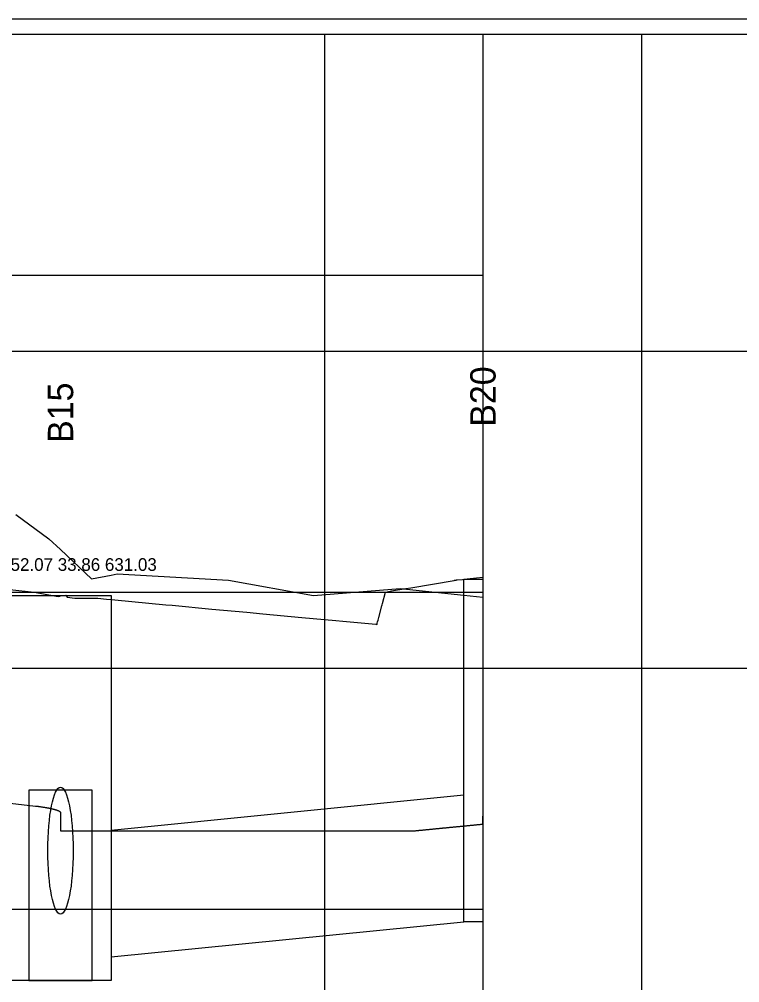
# Model space of a CAD drawing. Extents: x 2253035 to 2279930, y 13774972 to 13793443.
# Drawn here: x 2277850.3 to 2277907.1, y 13792716.5 to 13792792.4 of the extents above; entities that cross this region are included whole.
import ezdxf

# ---------------------------------------------------------------- set-up
doc = ezdxf.new("R2010")
doc.units = 0
for name, color, linetype in [('Default', 7, 'Continuous'), ('E_Utility_ATT_HH', 7, 'Continuous'), ('E_Utility_ATT_PR_PVC', 7, 'Continuous'), ('E_Utility_Telephone_Manhole Telephone_MHT_point', 7, 'Continuous'), ('E_Utility_Telephone_Telephone Pedestal_TPED_Description', 7, 'Continuous'), ('E_Utility_Water_Water Meter_WM_Description', 7, 'Continuous'), ('E_Utillity_Water_Water Line_12in', 7, 'Continuous'), ('E_Utillity_Water_Water Line_1in', 7, 'Continuous'), ('E_Utillity_Water_Water Line_4in', 7, 'Continuous'), ('E_Utillity_Water_Water Line_8in', 7, 'Continuous')]:
    doc.layers.add(name, color=color, linetype=linetype)

msp = doc.modelspace()

# ---------------------------------------------------------------- linework, layer by layer
at = {"layer": 'Default'}
for p, q in [((2277799.404, 13792772.266), (2277886.867, 13792772.266)), ((2277799.404, 13792747.266), (2277886.867, 13792747.266)), ((2277799.404, 13792722.266), (2277886.867, 13792722.266))]:
    msp.add_line(p, q, dxfattribs=at)
msp.add_lwpolyline([(2277799.404, 13792697.266), (2277799.404, 13792791.266), (2277886.867, 13792791.266), (2277886.867, 13792697.266)], close=True, dxfattribs=at)
at = {"layer": 'E_Utility_ATT_PR_PVC'}
msp.add_line((2277853.564, 13792729.873), (2277853.564, 13792728.442), dxfattribs=at)
for points in [[(2277811.207, 13792735.15), (2277851.594, 13792730.392), (2277851.646, 13792730.386), (2277851.695, 13792730.379), (2277851.743, 13792730.373), (2277851.79, 13792730.367), (2277851.835, 13792730.361), (2277851.88, 13792730.355), (2277851.923, 13792730.349), (2277851.966, 13792730.343), (2277852.008, 13792730.337), (2277852.049, 13792730.331), (2277852.089, 13792730.325), (2277852.128, 13792730.319), (2277852.166, 13792730.313), (2277852.204, 13792730.307), (2277852.241, 13792730.301), (2277852.278, 13792730.295), (2277852.313, 13792730.289), (2277852.349, 13792730.283), (2277852.383, 13792730.277), (2277852.417, 13792730.271), (2277852.45, 13792730.265), (2277852.483, 13792730.26), (2277852.515, 13792730.254), (2277852.546, 13792730.248), (2277852.577, 13792730.242), (2277852.607, 13792730.237), (2277852.637, 13792730.231), (2277852.666, 13792730.225), (2277852.695, 13792730.219), (2277852.723, 13792730.214), (2277852.75, 13792730.208), (2277852.777, 13792730.202), (2277852.804, 13792730.197), (2277852.83, 13792730.191), (2277852.855, 13792730.185), (2277852.88, 13792730.18), (2277852.904, 13792730.174), (2277852.928, 13792730.169), (2277852.952, 13792730.163), (2277852.975, 13792730.157), (2277852.997, 13792730.152), (2277853.019, 13792730.146), (2277853.041, 13792730.141), (2277853.062, 13792730.135), (2277853.082, 13792730.13), (2277853.102, 13792730.124), (2277853.122, 13792730.119), (2277853.141, 13792730.113), (2277853.16, 13792730.108), (2277853.178, 13792730.102), (2277853.196, 13792730.097), (2277853.213, 13792730.091), (2277853.23, 13792730.086), (2277853.247, 13792730.081), (2277853.263, 13792730.075), (2277853.278, 13792730.07), (2277853.294, 13792730.064), (2277853.308, 13792730.059), (2277853.323, 13792730.054), (2277853.336, 13792730.048), (2277853.35, 13792730.043), (2277853.363, 13792730.038), (2277853.375, 13792730.032), (2277853.388, 13792730.027), (2277853.399, 13792730.022), (2277853.411, 13792730.016), (2277853.422, 13792730.011), (2277853.432, 13792730.006), (2277853.442, 13792730.001), (2277853.452, 13792729.995), (2277853.461, 13792729.99), (2277853.47, 13792729.985), (2277853.478, 13792729.98), (2277853.486, 13792729.975), (2277853.494, 13792729.969), (2277853.501, 13792729.964), (2277853.508, 13792729.959), (2277853.514, 13792729.954), (2277853.52, 13792729.949), (2277853.526, 13792729.944), (2277853.531, 13792729.938), (2277853.536, 13792729.933), (2277853.541, 13792729.928), (2277853.545, 13792729.923), (2277853.548, 13792729.918), (2277853.551, 13792729.913), (2277853.554, 13792729.908), (2277853.557, 13792729.903), (2277853.559, 13792729.898), (2277853.561, 13792729.893), (2277853.562, 13792729.888), (2277853.563, 13792729.883), (2277853.564, 13792729.878), (2277853.564, 13792729.873)], [(2277853.564, 13792728.442), (2277853.614, 13792728.442), (2277853.664, 13792728.442), (2277853.714, 13792728.442), (2277853.764, 13792728.442), (2277853.815, 13792728.442), (2277853.865, 13792728.442), (2277853.915, 13792728.442), (2277853.965, 13792728.442), (2277854.015, 13792728.442), (2277854.065, 13792728.442), (2277854.115, 13792728.442), (2277854.166, 13792728.442), (2277854.216, 13792728.442), (2277854.266, 13792728.442), (2277854.316, 13792728.442), (2277854.366, 13792728.442), (2277854.416, 13792728.442), (2277854.466, 13792728.442), (2277854.516, 13792728.442), (2277854.567, 13792728.442), (2277854.617, 13792728.442), (2277854.667, 13792728.442), (2277854.717, 13792728.442), (2277854.767, 13792728.442), (2277854.817, 13792728.442), (2277854.867, 13792728.442), (2277854.917, 13792728.442), (2277854.967, 13792728.442), (2277855.018, 13792728.442), (2277855.068, 13792728.442), (2277855.118, 13792728.443), (2277855.168, 13792728.443), (2277855.218, 13792728.443), (2277855.268, 13792728.443), (2277855.318, 13792728.443), (2277855.368, 13792728.443), (2277855.418, 13792728.443), (2277855.468, 13792728.443), (2277855.518, 13792728.443), (2277855.568, 13792728.443), (2277855.618, 13792728.443), (2277855.668, 13792728.443), (2277855.719, 13792728.443), (2277855.769, 13792728.443), (2277855.819, 13792728.443), (2277855.869, 13792728.443), (2277855.919, 13792728.443), (2277855.969, 13792728.443), (2277856.019, 13792728.443), (2277856.069, 13792728.443), (2277856.119, 13792728.443), (2277856.169, 13792728.443), (2277856.219, 13792728.443), (2277856.269, 13792728.443), (2277856.319, 13792728.443), (2277856.369, 13792728.443), (2277856.419, 13792728.443), (2277856.469, 13792728.443), (2277856.519, 13792728.443), (2277856.569, 13792728.443), (2277856.619, 13792728.443), (2277856.669, 13792728.443), (2277856.719, 13792728.443), (2277856.769, 13792728.443), (2277856.819, 13792728.443), (2277856.869, 13792728.443), (2277856.919, 13792728.443), (2277856.969, 13792728.443), (2277857.019, 13792728.443), (2277857.069, 13792728.443), (2277857.12, 13792728.443), (2277857.17, 13792728.443), (2277857.22, 13792728.443), (2277857.27, 13792728.443), (2277857.32, 13792728.443), (2277857.37, 13792728.443), (2277857.42, 13792728.443), (2277857.47, 13792728.443), (2277857.52, 13792728.443), (2277857.57, 13792728.443), (2277857.62, 13792728.443), (2277857.67, 13792728.443), (2277857.72, 13792728.443), (2277857.769, 13792728.443), (2277857.819, 13792728.443), (2277857.869, 13792728.443), (2277857.919, 13792728.443), (2277857.969, 13792728.443), (2277858.019, 13792728.443), (2277858.069, 13792728.443), (2277858.119, 13792728.443), (2277858.169, 13792728.443), (2277858.219, 13792728.443), (2277858.269, 13792728.443), (2277858.319, 13792728.443), (2277858.369, 13792728.443), (2277858.419, 13792728.443), (2277858.469, 13792728.443), (2277858.519, 13792728.443), (2277858.569, 13792728.443), (2277858.619, 13792728.443), (2277858.669, 13792728.443), (2277858.719, 13792728.443), (2277858.769, 13792728.443), (2277858.819, 13792728.443), (2277858.869, 13792728.443), (2277858.919, 13792728.443), (2277858.969, 13792728.443), (2277859.019, 13792728.443), (2277859.069, 13792728.443), (2277859.119, 13792728.443), (2277859.169, 13792728.443), (2277859.219, 13792728.443), (2277859.269, 13792728.443), (2277859.318, 13792728.443), (2277859.368, 13792728.443), (2277859.418, 13792728.443), (2277859.468, 13792728.443), (2277859.518, 13792728.443), (2277859.568, 13792728.443), (2277859.618, 13792728.443), (2277859.668, 13792728.443), (2277859.718, 13792728.443), (2277859.768, 13792728.443), (2277859.818, 13792728.443), (2277859.868, 13792728.443), (2277859.918, 13792728.443), (2277859.968, 13792728.442), (2277860.018, 13792728.442), (2277860.067, 13792728.442), (2277860.117, 13792728.442), (2277860.167, 13792728.442), (2277860.217, 13792728.442), (2277860.267, 13792728.442), (2277860.317, 13792728.442), (2277860.367, 13792728.442), (2277860.417, 13792728.442), (2277860.467, 13792728.442), (2277860.517, 13792728.442), (2277860.567, 13792728.442), (2277860.617, 13792728.442), (2277860.666, 13792728.442), (2277860.716, 13792728.442), (2277860.766, 13792728.442), (2277860.816, 13792728.442), (2277860.866, 13792728.442), (2277860.916, 13792728.442), (2277860.966, 13792728.442), (2277861.016, 13792728.442), (2277861.066, 13792728.442), (2277861.116, 13792728.442), (2277861.165, 13792728.442), (2277861.215, 13792728.442), (2277861.265, 13792728.442), (2277861.315, 13792728.442), (2277861.365, 13792728.442), (2277861.415, 13792728.442), (2277861.465, 13792728.442), (2277861.515, 13792728.442), (2277861.565, 13792728.442), (2277861.614, 13792728.442), (2277861.664, 13792728.442), (2277861.714, 13792728.442), (2277861.764, 13792728.442), (2277861.814, 13792728.442), (2277861.864, 13792728.442), (2277861.914, 13792728.442), (2277861.964, 13792728.442), (2277862.014, 13792728.442), (2277862.063, 13792728.442), (2277862.113, 13792728.442), (2277862.163, 13792728.442), (2277862.213, 13792728.442), (2277862.263, 13792728.442), (2277862.313, 13792728.442), (2277862.363, 13792728.442), (2277862.412, 13792728.442), (2277862.462, 13792728.442), (2277862.512, 13792728.442), (2277862.562, 13792728.442), (2277862.612, 13792728.442), (2277862.662, 13792728.442), (2277862.712, 13792728.442), (2277862.761, 13792728.442), (2277862.811, 13792728.442), (2277862.861, 13792728.442), (2277862.911, 13792728.442), (2277862.961, 13792728.442), (2277863.011, 13792728.442), (2277863.061, 13792728.442), (2277863.11, 13792728.442), (2277863.16, 13792728.442), (2277863.21, 13792728.442), (2277863.26, 13792728.442), (2277863.31, 13792728.442), (2277863.36, 13792728.442), (2277863.41, 13792728.442), (2277863.459, 13792728.442), (2277863.509, 13792728.442), (2277863.559, 13792728.442), (2277863.609, 13792728.442), (2277863.659, 13792728.442), (2277863.709, 13792728.442), (2277863.758, 13792728.442), (2277863.808, 13792728.442), (2277863.858, 13792728.442), (2277863.908, 13792728.442), (2277863.958, 13792728.442), (2277864.007, 13792728.442), (2277864.057, 13792728.442), (2277864.107, 13792728.441), (2277864.157, 13792728.441), (2277864.207, 13792728.441), (2277864.257, 13792728.441), (2277864.306, 13792728.441), (2277864.356, 13792728.441), (2277864.406, 13792728.441), (2277864.456, 13792728.441), (2277864.506, 13792728.441), (2277864.555, 13792728.441), (2277864.605, 13792728.441), (2277864.655, 13792728.441), (2277864.705, 13792728.441), (2277864.755, 13792728.441), (2277864.805, 13792728.441), (2277864.854, 13792728.441), (2277864.904, 13792728.441), (2277864.954, 13792728.441), (2277865.004, 13792728.441), (2277865.054, 13792728.441), (2277865.103, 13792728.441), (2277865.153, 13792728.441), (2277865.203, 13792728.441), (2277865.253, 13792728.441), (2277865.303, 13792728.441), (2277865.352, 13792728.441), (2277865.402, 13792728.441), (2277865.452, 13792728.441), (2277865.502, 13792728.441), (2277865.551, 13792728.441), (2277865.601, 13792728.441), (2277865.651, 13792728.441), (2277865.701, 13792728.441), (2277865.751, 13792728.441), (2277865.8, 13792728.441), (2277865.85, 13792728.441), (2277865.9, 13792728.441), (2277865.95, 13792728.441), (2277865.999, 13792728.441), (2277866.049, 13792728.441), (2277866.099, 13792728.441), (2277866.149, 13792728.441), (2277866.199, 13792728.441), (2277866.248, 13792728.441), (2277866.298, 13792728.441), (2277866.348, 13792728.441), (2277866.398, 13792728.441), (2277866.447, 13792728.441), (2277866.497, 13792728.441), (2277866.547, 13792728.44), (2277866.597, 13792728.44), (2277866.646, 13792728.44), (2277866.696, 13792728.44), (2277866.746, 13792728.44), (2277866.796, 13792728.44), (2277866.845, 13792728.44), (2277866.895, 13792728.44), (2277866.945, 13792728.44), (2277866.995, 13792728.44), (2277867.044, 13792728.44), (2277867.094, 13792728.44), (2277867.144, 13792728.44), (2277867.194, 13792728.44), (2277867.243, 13792728.44), (2277867.293, 13792728.44), (2277867.343, 13792728.44), (2277867.393, 13792728.44), (2277867.442, 13792728.44), (2277867.492, 13792728.44), (2277867.542, 13792728.44), (2277867.592, 13792728.44), (2277867.641, 13792728.44), (2277867.691, 13792728.44), (2277867.741, 13792728.44), (2277867.791, 13792728.44), (2277867.84, 13792728.44), (2277867.89, 13792728.44), (2277867.94, 13792728.44), (2277867.989, 13792728.44), (2277868.039, 13792728.44), (2277868.089, 13792728.44), (2277868.139, 13792728.44), (2277868.188, 13792728.44), (2277868.238, 13792728.44), (2277868.288, 13792728.44), (2277868.337, 13792728.44), (2277868.387, 13792728.44), (2277868.437, 13792728.439), (2277868.487, 13792728.439), (2277868.536, 13792728.439), (2277868.586, 13792728.439), (2277868.636, 13792728.439), (2277868.685, 13792728.439), (2277868.735, 13792728.439), (2277868.785, 13792728.439), (2277868.835, 13792728.439), (2277868.884, 13792728.439), (2277868.934, 13792728.439), (2277868.984, 13792728.439), (2277869.033, 13792728.439), (2277869.083, 13792728.439), (2277869.133, 13792728.439), (2277869.182, 13792728.439), (2277869.232, 13792728.439), (2277869.282, 13792728.439), (2277869.332, 13792728.439), (2277869.381, 13792728.439), (2277869.431, 13792728.439), (2277869.481, 13792728.439), (2277869.53, 13792728.439), (2277869.58, 13792728.439), (2277869.63, 13792728.439), (2277869.679, 13792728.439), (2277869.729, 13792728.439), (2277869.779, 13792728.439), (2277869.828, 13792728.439), (2277869.878, 13792728.439), (2277869.928, 13792728.439), (2277869.977, 13792728.439), (2277870.027, 13792728.438), (2277870.077, 13792728.438), (2277870.126, 13792728.438), (2277870.176, 13792728.438), (2277870.226, 13792728.438), (2277870.275, 13792728.438), (2277870.325, 13792728.438), (2277870.375, 13792728.438), (2277870.424, 13792728.438), (2277870.474, 13792728.438), (2277870.524, 13792728.438), (2277870.573, 13792728.438), (2277870.623, 13792728.438), (2277870.673, 13792728.438), (2277870.722, 13792728.438), (2277870.772, 13792728.438), (2277870.822, 13792728.438), (2277870.871, 13792728.438), (2277870.921, 13792728.438), (2277870.97, 13792728.438), (2277871.02, 13792728.438), (2277871.07, 13792728.438), (2277871.119, 13792728.438), (2277871.169, 13792728.438), (2277871.219, 13792728.438), (2277871.268, 13792728.438), (2277871.318, 13792728.438), (2277871.368, 13792728.438), (2277871.417, 13792728.437), (2277871.467, 13792728.437), (2277871.516, 13792728.437), (2277871.566, 13792728.437), (2277871.616, 13792728.437), (2277871.665, 13792728.437), (2277871.715, 13792728.437), (2277871.765, 13792728.437), (2277871.814, 13792728.437), (2277871.864, 13792728.437), (2277871.913, 13792728.437), (2277871.963, 13792728.437), (2277872.013, 13792728.437), (2277872.062, 13792728.437), (2277872.112, 13792728.437), (2277872.161, 13792728.437), (2277872.211, 13792728.437), (2277872.261, 13792728.437), (2277872.31, 13792728.437), (2277872.36, 13792728.437), (2277872.409, 13792728.437), (2277872.459, 13792728.437), (2277872.509, 13792728.437), (2277872.558, 13792728.437), (2277872.608, 13792728.437), (2277872.657, 13792728.437), (2277872.707, 13792728.436), (2277872.757, 13792728.436), (2277872.806, 13792728.436), (2277872.856, 13792728.436), (2277872.905, 13792728.436), (2277872.955, 13792728.436), (2277873.004, 13792728.436), (2277873.054, 13792728.436), (2277873.104, 13792728.436), (2277873.153, 13792728.436), (2277873.203, 13792728.436), (2277873.252, 13792728.436), (2277873.302, 13792728.436), (2277873.351, 13792728.436), (2277873.401, 13792728.436), (2277873.451, 13792728.436), (2277873.5, 13792728.436), (2277873.55, 13792728.436), (2277873.599, 13792728.436), (2277873.649, 13792728.436), (2277873.698, 13792728.436), (2277873.748, 13792728.436), (2277873.798, 13792728.436), (2277873.847, 13792728.435), (2277873.897, 13792728.435), (2277873.946, 13792728.435), (2277873.996, 13792728.435), (2277874.045, 13792728.435), (2277874.095, 13792728.435), (2277874.144, 13792728.435), (2277874.194, 13792728.435), (2277874.243, 13792728.435), (2277874.293, 13792728.435), (2277874.343, 13792728.435), (2277874.392, 13792728.435), (2277874.442, 13792728.435), (2277874.491, 13792728.435), (2277874.541, 13792728.435), (2277874.59, 13792728.435), (2277874.64, 13792728.435), (2277874.689, 13792728.435), (2277874.739, 13792728.435), (2277874.788, 13792728.435), (2277874.838, 13792728.435), (2277874.887, 13792728.435), (2277874.937, 13792728.434), (2277874.986, 13792728.434), (2277875.036, 13792728.434), (2277875.085, 13792728.434), (2277875.135, 13792728.434), (2277875.184, 13792728.434), (2277875.234, 13792728.434), (2277875.283, 13792728.434), (2277875.333, 13792728.434), (2277875.382, 13792728.434), (2277875.432, 13792728.434), (2277875.481, 13792728.434), (2277875.531, 13792728.434), (2277875.58, 13792728.434), (2277875.63, 13792728.434), (2277875.679, 13792728.434), (2277875.729, 13792728.434), (2277875.778, 13792728.434), (2277875.828, 13792728.434), (2277875.877, 13792728.434), (2277875.927, 13792728.433), (2277875.976, 13792728.433), (2277876.026, 13792728.433), (2277876.075, 13792728.433), (2277876.125, 13792728.433), (2277876.174, 13792728.433), (2277876.224, 13792728.433), (2277876.273, 13792728.433), (2277876.323, 13792728.433), (2277876.372, 13792728.433), (2277876.421, 13792728.433), (2277876.471, 13792728.433), (2277876.52, 13792728.433), (2277876.57, 13792728.433), (2277876.619, 13792728.433), (2277876.669, 13792728.433), (2277876.718, 13792728.433), (2277876.768, 13792728.433), (2277876.817, 13792728.432), (2277876.867, 13792728.432), (2277876.916, 13792728.432), (2277876.965, 13792728.432), (2277877.015, 13792728.432), (2277877.064, 13792728.432), (2277877.114, 13792728.432), (2277877.163, 13792728.432), (2277877.213, 13792728.432), (2277877.262, 13792728.432), (2277877.311, 13792728.432), (2277877.361, 13792728.432), (2277877.41, 13792728.432), (2277877.46, 13792728.432), (2277877.509, 13792728.432), (2277877.559, 13792728.432), (2277877.608, 13792728.432), (2277877.657, 13792728.432), (2277877.707, 13792728.431), (2277877.756, 13792728.431), (2277877.806, 13792728.431), (2277877.855, 13792728.431), (2277877.904, 13792728.431), (2277877.954, 13792728.431), (2277878.003, 13792728.431), (2277878.053, 13792728.431), (2277878.102, 13792728.431), (2277878.151, 13792728.431), (2277878.201, 13792728.431), (2277878.25, 13792728.431), (2277878.3, 13792728.431), (2277878.349, 13792728.431), (2277878.398, 13792728.431), (2277878.448, 13792728.431), (2277878.497, 13792728.431), (2277878.547, 13792728.43), (2277878.596, 13792728.43), (2277878.645, 13792728.43), (2277878.695, 13792728.43), (2277878.744, 13792728.43), (2277878.793, 13792728.43), (2277878.843, 13792728.43), (2277878.892, 13792728.43), (2277878.941, 13792728.43), (2277878.991, 13792728.43), (2277879.04, 13792728.43), (2277879.09, 13792728.43), (2277879.139, 13792728.43), (2277879.188, 13792728.43), (2277879.238, 13792728.43), (2277879.287, 13792728.429), (2277879.336, 13792728.429), (2277879.386, 13792728.429), (2277879.435, 13792728.429), (2277879.484, 13792728.429), (2277879.534, 13792728.429), (2277879.583, 13792728.429), (2277879.632, 13792728.429), (2277879.682, 13792728.429), (2277879.731, 13792728.429), (2277879.78, 13792728.429), (2277879.83, 13792728.429), (2277879.879, 13792728.429), (2277879.928, 13792728.429), (2277879.978, 13792728.429), (2277880.027, 13792728.428), (2277880.076, 13792728.428), (2277880.126, 13792728.428), (2277880.175, 13792728.428), (2277880.224, 13792728.428), (2277880.273, 13792728.428), (2277880.323, 13792728.428), (2277880.372, 13792728.428), (2277880.421, 13792728.428), (2277880.471, 13792728.428), (2277880.52, 13792728.428), (2277880.569, 13792728.428), (2277880.618, 13792728.428), (2277880.668, 13792728.428), (2277880.717, 13792728.427), (2277880.766, 13792728.427), (2277880.816, 13792728.427), (2277880.865, 13792728.427), (2277880.914, 13792728.427), (2277880.963, 13792728.427), (2277881.013, 13792728.427), (2277881.062, 13792728.427), (2277881.111, 13792728.427), (2277881.16, 13792728.427), (2277881.21, 13792728.427), (2277881.259, 13792728.427), (2277881.308, 13792728.427), (2277881.357, 13792728.427), (2277881.407, 13792728.43), (2277881.456, 13792728.435), (2277881.505, 13792728.44), (2277881.554, 13792728.445), (2277881.604, 13792728.45), (2277881.653, 13792728.455), (2277881.702, 13792728.459), (2277881.751, 13792728.464), (2277881.801, 13792728.469), (2277881.85, 13792728.474), (2277881.899, 13792728.479), (2277881.948, 13792728.484), (2277881.997, 13792728.489), (2277882.047, 13792728.493), (2277882.096, 13792728.498), (2277882.145, 13792728.503), (2277882.194, 13792728.508), (2277882.243, 13792728.513), (2277882.293, 13792728.518), (2277882.342, 13792728.522), (2277882.391, 13792728.527), (2277882.44, 13792728.532), (2277882.489, 13792728.537), (2277882.539, 13792728.542), (2277882.588, 13792728.547), (2277882.637, 13792728.551), (2277882.686, 13792728.556), (2277882.735, 13792728.561), (2277882.785, 13792728.566), (2277882.834, 13792728.571), (2277882.883, 13792728.576), (2277882.932, 13792728.58), (2277882.981, 13792728.585), (2277883.03, 13792728.59), (2277883.08, 13792728.595), (2277883.129, 13792728.6), (2277883.178, 13792728.605), (2277883.227, 13792728.609), (2277883.276, 13792728.614), (2277883.325, 13792728.619), (2277883.374, 13792728.624), (2277883.424, 13792728.629), (2277883.473, 13792728.634), (2277883.522, 13792728.638), (2277883.571, 13792728.643), (2277883.62, 13792728.648), (2277883.669, 13792728.653), (2277883.718, 13792728.658), (2277883.767, 13792728.663), (2277883.817, 13792728.667), (2277883.866, 13792728.672), (2277883.915, 13792728.677), (2277883.964, 13792728.682), (2277884.013, 13792728.687), (2277884.062, 13792728.691), (2277884.111, 13792728.696), (2277884.16, 13792728.701), (2277884.209, 13792728.706), (2277884.258, 13792728.711), (2277884.308, 13792728.716), (2277884.357, 13792728.72), (2277884.406, 13792728.725), (2277884.455, 13792728.73), (2277884.504, 13792728.735), (2277884.553, 13792728.74), (2277884.602, 13792728.744), (2277884.651, 13792728.749), (2277884.7, 13792728.754), (2277884.749, 13792728.759), (2277884.798, 13792728.764), (2277884.847, 13792728.769), (2277884.896, 13792728.773), (2277884.945, 13792728.778), (2277884.994, 13792728.783), (2277885.043, 13792728.788), (2277885.092, 13792728.793), (2277885.142, 13792728.797), (2277885.191, 13792728.802), (2277885.24, 13792728.807), (2277885.289, 13792728.812), (2277885.338, 13792728.817), (2277885.387, 13792728.821), (2277885.436, 13792728.826), (2277885.485, 13792728.831), (2277885.534, 13792728.836), (2277885.583, 13792728.841), (2277885.632, 13792728.845), (2277885.681, 13792728.85), (2277885.73, 13792728.855), (2277885.779, 13792728.86), (2277885.828, 13792728.865), (2277885.877, 13792728.869), (2277885.926, 13792728.874), (2277885.975, 13792728.879), (2277886.024, 13792728.884), (2277886.073, 13792728.889), (2277886.121, 13792728.893), (2277886.17, 13792728.898), (2277886.219, 13792728.903), (2277886.268, 13792728.908), (2277886.317, 13792728.913), (2277886.366, 13792728.917), (2277886.415, 13792728.922), (2277886.464, 13792728.927), (2277886.513, 13792728.932), (2277886.562, 13792728.936), (2277886.611, 13792728.941), (2277886.66, 13792728.946), (2277886.709, 13792728.951), (2277886.758, 13792728.956), (2277886.807, 13792728.96), (2277886.856, 13792728.965), (2277886.867, 13792728.963), (2277886.867, 13792729.592)]]:
    msp.add_lwpolyline(points, dxfattribs=at)
at = {"layer": 'E_Utility_Telephone_Manhole Telephone_MHT_point'}
for p, q in [((2277749.404, 13792791.266), (2278074.404, 13792791.266)), ((2277874.404, 13792491.266), (2277874.404, 13792791.266)), ((2277899.404, 13792491.266), (2277899.404, 13792791.266)), ((2277749.404, 13792766.266), (2278074.404, 13792766.266)), ((2277749.404, 13792741.266), (2278074.404, 13792741.266))]:
    msp.add_line(p, q, dxfattribs=at)
at = {"layer": 'E_Utility_Water_Water Meter_WM_Description'}
msp.add_lwpolyline([(2278133.026, 13792792.439), (2277749.404, 13792792.439), (2277749.404, 13792491.266), (2278133.026, 13792491.266)], close=True, dxfattribs=at)
at = {"layer": 'E_Utillity_Water_Water Line_12in'}
for points in [[(2277885.367, 13792748.279), (2277886.867, 13792748.279), (2277886.867, 13792721.266), (2277885.367, 13792721.266)], [(2277849.564, 13792747.003), (2277857.564, 13792747.003), (2277857.564, 13792716.641), (2277849.564, 13792716.641)]]:
    msp.add_lwpolyline(points, close=True, dxfattribs=at)
at = {"layer": 'E_Utillity_Water_Water Line_1in'}
msp.add_lwpolyline([(2277850.03, 13792753.376), (2277852.656, 13792751.471), (2277853.564, 13792750.612), (2277853.564, 13792750.612), (2277856.002, 13792748.307), (2277857.564, 13792748.604), (2277857.564, 13792748.604), (2277858.03, 13792748.695), (2277866.808, 13792748.204), (2277873.505, 13792746.995), (2277880.34, 13792747.538), (2277885.367, 13792747.029), (2277885.367, 13792747.029), (2277886.867, 13792746.867)], dxfattribs=at)
at = {"layer": 'E_Utillity_Water_Water Line_4in'}
for p, q in [((2277857.564, 13792728.486), (2277885.367, 13792731.266)), ((2277857.564, 13792718.486), (2277885.367, 13792721.266))]:
    msp.add_line(p, q, dxfattribs=at)
msp.add_lwpolyline([(2277851.064, 13792716.641), (2277856.064, 13792716.641), (2277856.064, 13792731.641), (2277851.064, 13792731.641)], close=True, dxfattribs=at)
msp.add_ellipse((2277853.564, 13792726.869), major_axis=(0, 5), ratio=0.2, dxfattribs=at)
at = {"layer": 'E_Utillity_Water_Water Line_8in'}
msp.add_lwpolyline([(2277849.564, 13792747.458), (2277851.5, 13792747.266), (2277853.386, 13792746.917), (2277853.435, 13792746.951), (2277853.536, 13792746.952), (2277853.538, 13792747.002), (2277853.551, 13792747.003), (2277853.564, 13792747.003), (2277853.564, 13792747.003), (2277853.98, 13792747.024), (2277854.086, 13792746.87), (2277854.706, 13792746.776), (2277856.501, 13792746.773), (2277857.194, 13792746.704), (2277857.564, 13792746.668), (2277857.564, 13792746.668), (2277857.854, 13792746.64), (2277861.862, 13792746.266), (2277862.361, 13792746.22), (2277865.491, 13792745.928), (2277868.266, 13792745.669), (2277869.519, 13792745.554), (2277872.583, 13792745.266), (2277875.26, 13792745.016), (2277875.81, 13792744.966), (2277878.417, 13792744.727), (2277878.428, 13792744.726), (2277878.514, 13792744.719), (2277878.516, 13792744.728), (2277878.519, 13792744.736), (2277878.541, 13792744.82), (2277878.568, 13792744.924), (2277878.602, 13792745.053), (2277878.658, 13792745.266), (2277878.891, 13792746.17), (2277878.916, 13792746.266), (2277878.941, 13792746.365), (2277879.174, 13792747.266), (2277879.646, 13792747.356), (2277880.787, 13792747.541), (2277881.18, 13792747.608), (2277884.59, 13792748.188), (2277884.622, 13792748.194), (2277884.72, 13792748.21), (2277884.753, 13792748.214), (2277884.754, 13792748.214), (2277884.778, 13792748.216), (2277884.844, 13792748.223), (2277885.253, 13792748.266), (2277885.367, 13792748.279), (2277885.367, 13792748.279), (2277886.867, 13792748.431)], dxfattribs=at)

# ---------------------------------------------------------------- texts
at = {"layer": 'E_Utility_ATT_HH'}
for s, p in [('B20', (2277887.867, 13792760.304)), ('B15', (2277854.564, 13792759.028))]:
    msp.add_text(s, height=2, rotation=90, dxfattribs=at).set_placement(p)
at = {"layer": 'E_Utility_Telephone_Telephone Pedestal_TPED_Description'}
msp.add_text('CI-B20 144+52.07 33.86 631.03', height=1, rotation=0, dxfattribs=at).set_placement((2277842.083, 13792748.936))

doc.saveas('drawing.dxf')
